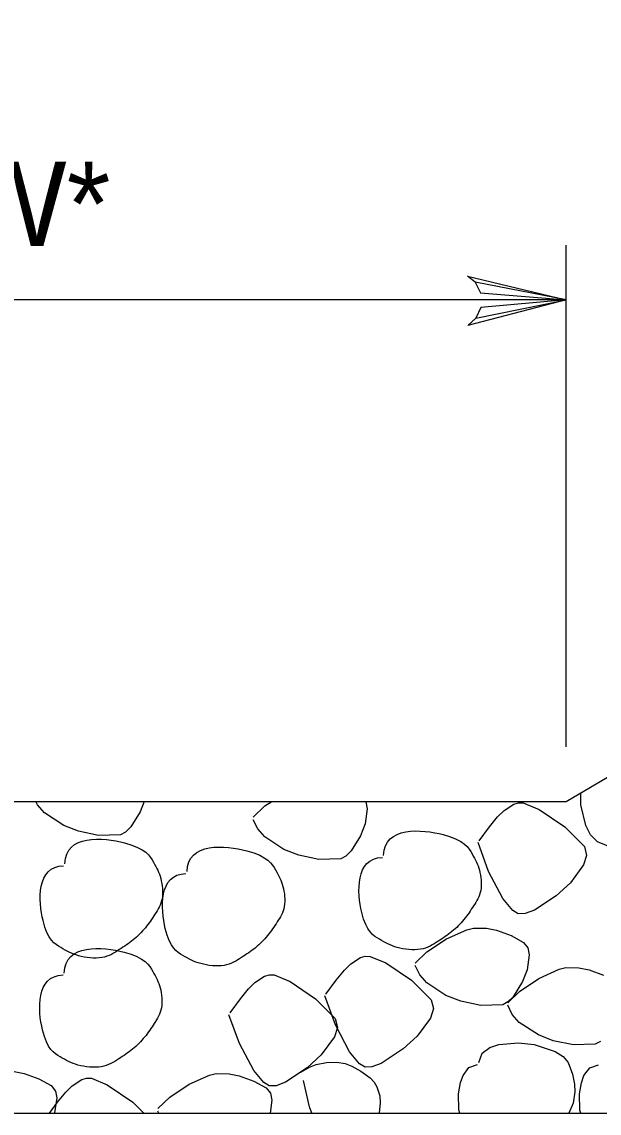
# Model space of a CAD drawing. Extents: x 636462 to 638208, y 299350 to 300538.
# Drawn here: x 637766.43 to 637786.9, y 299583.43 to 299622.12 of the extents above; entities that cross this region are included whole.
import ezdxf

# ---------------------------------------------------------------- set-up
doc = ezdxf.new("R2010")
doc.units = 0
doc.layers.add('Default', color=7, linetype='Continuous')

msp = doc.modelspace()

# ---------------------------------------------------------------- linework, layer by layer
at = {"layer": 'Default'}
for p, q in [((637785.737, 299596.416), (637785.737, 299614.199)), ((637785.737, 299612.265), (637747.043, 299612.265)), ((637786.257, 299594.359), (637786.248, 299594.783)), ((637766.984, 299594.355), (637766.919, 299594.481)), ((637770.77, 299594.481), (637770.63, 299594.113)), ((637775.048, 299594.318), (637775.296, 299594.481)), ((637778.613, 299594.481), (637778.629, 299594.461)), ((637778.629, 299594.461), (637778.675, 299594.214)), ((637783.53, 299594.154), (637783.874, 299594.382)), ((637783.874, 299594.382), (637784.044, 299594.431)), ((637784.044, 299594.431), (637784.214, 299594.424)), ((637784.214, 299594.424), (637784.779, 299594.198)), ((637767.233, 299594.069), (637766.984, 299594.355)), ((637767.914, 299593.625), (637767.233, 299594.069)), ((637770.63, 299594.113), (637770.296, 299593.574)), ((637774.633, 299593.919), (637775.048, 299594.318)), ((637778.675, 299594.214), (637778.599, 299593.685)), ((637783.302, 299593.929), (637783.53, 299594.154)), ((637784.779, 299594.198), (637785.682, 299593.579)), ((637786.428, 299593.627), (637786.257, 299594.359)), ((637768.442, 299593.422), (637767.914, 299593.625)), ((637774.794, 299593.507), (637774.633, 299593.832)), ((637778.599, 299593.685), (637778.44, 299593.265)), ((637783.01, 299593.574), (637783.302, 299593.929)), ((637786.598, 299593.293), (637786.428, 299593.627)), ((637769.151, 299593.272), (637768.442, 299593.422)), ((637769.925, 299593.295), (637769.151, 299593.272)), ((637770.109, 299593.392), (637769.925, 299593.295)), ((637770.296, 299593.574), (637770.109, 299593.392)), ((637775.043, 299593.222), (637774.794, 299593.507)), ((637775.725, 299592.775), (637775.043, 299593.222)), ((637778.44, 299593.265), (637778.106, 299592.726)), ((637782.651, 299593.083), (637783.01, 299593.574)), ((637785.682, 299593.579), (637786.379, 299592.883)), ((637786.849, 299593.047), (637786.598, 299593.293)), ((637782.984, 299591.996), (637782.607, 299593.017)), ((637786.379, 299592.883), (637786.46, 299592.567)), ((637787.303, 299592.862), (637786.849, 299593.047)), ((637776.254, 299592.572), (637775.725, 299592.775)), ((637776.962, 299592.422), (637776.254, 299592.572)), ((637777.738, 299592.448), (637776.962, 299592.422)), ((637777.92, 299592.542), (637777.738, 299592.448)), ((637778.106, 299592.726), (637777.92, 299592.542)), ((637786.46, 299592.567), (637786.354, 299592.233)), ((637786.354, 299592.233), (637785.882, 299591.593)), ((637783.487, 299591.036), (637782.984, 299591.996)), ((637785.882, 299591.593), (637785.384, 299591.137)), ((637783.839, 299590.61), (637783.487, 299591.036)), ((637785.384, 299591.137), (637784.608, 299590.626)), ((637784.035, 299590.495), (637783.839, 299590.61)), ((637784.608, 299590.626), (637784.279, 299590.501)), ((637784.279, 299590.501), (637784.035, 299590.495)), ((637781.49, 299589.606), (637782.208, 299589.93)), ((637782.208, 299589.93), (637782.446, 299589.99)), ((637782.446, 299589.99), (637782.904, 299589.986)), ((637782.904, 299589.986), (637783.263, 299589.91)), ((637783.263, 299589.91), (637783.784, 299589.721)), ((637780.794, 299589.145), (637781.49, 299589.606)), ((637783.784, 299589.721), (637784.219, 299589.483)), ((637784.219, 299589.483), (637784.373, 299589.288)), ((637778.436, 299588.947), (637778.608, 299588.995)), ((637778.608, 299588.995), (637778.776, 299588.986)), ((637778.776, 299588.986), (637779.341, 299588.76)), ((637780.377, 299588.746), (637780.794, 299589.145)), ((637784.422, 299589.041), (637784.346, 299588.509)), ((637784.373, 299589.288), (637784.422, 299589.041)), ((637777.867, 299588.491), (637778.092, 299588.716)), ((637778.092, 299588.716), (637778.436, 299588.947)), ((637779.341, 299588.76), (637780.244, 299588.141)), ((637780.538, 299588.332), (637780.377, 299588.657)), ((637785.49, 299588.528), (637785.725, 299588.585)), ((637785.725, 299588.585), (637786.184, 299588.581)), ((637786.184, 299588.581), (637786.545, 299588.507)), ((637774.695, 299588.055), (637775.038, 299588.283)), ((637775.038, 299588.283), (637775.211, 299588.332)), ((637775.211, 299588.332), (637775.379, 299588.325)), ((637775.379, 299588.325), (637775.944, 299588.097)), ((637777.574, 299588.138), (637777.867, 299588.491)), ((637780.787, 299588.049), (637780.538, 299588.332)), ((637784.074, 299587.742), (637784.769, 299588.203)), ((637784.346, 299588.509), (637784.187, 299588.09)), ((637784.769, 299588.203), (637785.49, 299588.528)), ((637786.545, 299588.507), (637787.063, 299588.318)), ((637774.177, 299587.475), (637774.467, 299587.83)), ((637774.467, 299587.83), (637774.695, 299588.055)), ((637775.944, 299588.097), (637776.846, 299587.48)), ((637777.213, 299587.648), (637777.574, 299588.138)), ((637780.244, 299588.141), (637780.942, 299587.447)), ((637781.469, 299587.602), (637780.787, 299588.049)), ((637784.187, 299588.09), (637783.85, 299587.551)), ((637773.815, 299586.984), (637774.177, 299587.475)), ((637776.846, 299587.48), (637777.544, 299586.784)), ((637777.549, 299586.561), (637777.169, 299587.581)), ((637780.942, 299587.447), (637781.024, 299587.132)), ((637781.999, 299587.399), (637781.469, 299587.602)), ((637783.659, 299587.344), (637784.074, 299587.742)), ((637783.85, 299587.551), (637783.664, 299587.369)), ((637781.024, 299587.132), (637780.918, 299586.798)), ((637782.706, 299587.249), (637781.999, 299587.399)), ((637783.482, 299587.272), (637782.706, 299587.249)), ((637783.664, 299587.369), (637783.482, 299587.272)), ((637783.821, 299586.929), (637783.659, 299587.254)), ((637774.149, 299585.897), (637773.772, 299586.918)), ((637777.544, 299586.784), (637777.627, 299586.469)), ((637780.918, 299586.798), (637780.444, 299586.158)), ((637784.067, 299586.644), (637783.821, 299586.929)), ((637784.749, 299586.199), (637784.067, 299586.644)), ((637777.627, 299586.469), (637777.521, 299586.135)), ((637778.049, 299585.6), (637777.549, 299586.561)), ((637774.651, 299584.937), (637774.149, 299585.897)), ((637777.521, 299586.135), (637777.047, 299585.494)), ((637780.444, 299586.158), (637779.949, 299585.702)), ((637783.351, 299585.865), (637784.046, 299585.92)), ((637784.046, 299585.92), (637784.599, 299585.856)), ((637785.278, 299585.996), (637784.749, 299586.199)), ((637785.988, 299585.847), (637785.278, 299585.996)), ((637786.762, 299585.87), (637785.988, 299585.847)), ((637786.946, 299585.966), (637786.762, 299585.87)), ((637777.047, 299585.494), (637776.549, 299585.038)), ((637778.403, 299585.174), (637778.049, 299585.6)), ((637779.949, 299585.702), (637779.17, 299585.19)), ((637782.637, 299585.218), (637782.759, 299585.554)), ((637782.759, 299585.554), (637783.026, 299585.757)), ((637783.026, 299585.757), (637783.351, 299585.865)), ((637784.599, 299585.856), (637785.343, 299585.614)), ((637785.343, 299585.614), (637785.622, 299585.432)), ((637776.632, 299585.054), (637776.872, 299585.146)), ((637776.872, 299585.146), (637777.236, 299585.222)), ((637777.236, 299585.222), (637777.597, 299585.236)), ((637777.597, 299585.236), (637777.901, 299585.183)), ((637777.901, 299585.183), (637778.127, 299585.098)), ((637778.127, 299585.098), (637778.456, 299584.914)), ((637778.599, 299585.057), (637778.403, 299585.174)), ((637779.17, 299585.19), (637778.841, 299585.064)), ((637782.287, 299585.043), (637782.591, 299585.151)), ((637785.622, 299585.432), (637785.806, 299585.218)), ((637785.806, 299585.218), (637785.963, 299584.812)), ((637786.578, 299585.034), (637786.882, 299585.142)), ((637766.15, 299584.909), (637766.51, 299584.833)), ((637766.51, 299584.833), (637767.028, 299584.644)), ((637772.367, 299584.449), (637773.085, 299584.773)), ((637773.085, 299584.773), (637773.32, 299584.831)), ((637773.32, 299584.831), (637773.781, 299584.826)), ((637773.781, 299584.826), (637774.14, 299584.753)), ((637774.14, 299584.753), (637774.658, 299584.564)), ((637775.006, 299584.511), (637774.651, 299584.937)), ((637776.549, 299585.038), (637775.773, 299584.527)), ((637776.324, 299584.879), (637776.632, 299585.054)), ((637778.456, 299584.914), (637778.779, 299584.677)), ((637778.841, 299585.064), (637778.599, 299585.057)), ((637781.985, 299584.513), (637782.075, 299584.766)), ((637782.075, 299584.766), (637782.287, 299585.043)), ((637785.963, 299584.812), (637786.027, 299584.46)), ((637786.276, 299584.506), (637786.366, 299584.76)), ((637786.366, 299584.76), (637786.578, 299585.034)), ((637767.028, 299584.644), (637767.463, 299584.407)), ((637767.463, 299584.407), (637767.62, 299584.211)), ((637767.984, 299584.168), (637768.209, 299584.393)), ((637768.209, 299584.393), (637768.552, 299584.621)), ((637768.552, 299584.621), (637768.725, 299584.67)), ((637768.725, 299584.67), (637768.893, 299584.663)), ((637768.893, 299584.663), (637769.458, 299584.435)), ((637769.458, 299584.435), (637770.361, 299583.817)), ((637771.671, 299583.988), (637772.367, 299584.449)), ((637774.658, 299584.564), (637775.096, 299584.327)), ((637775.2, 299584.393), (637775.006, 299584.511)), ((637775.096, 299584.327), (637775.25, 299584.131)), ((637775.444, 299584.4), (637775.2, 299584.393)), ((637775.773, 299584.527), (637775.444, 299584.4)), ((637776.632, 299583.656), (637776.413, 299584.589)), ((637778.779, 299584.677), (637778.926, 299584.525)), ((637778.926, 299584.525), (637779.021, 299584.363)), ((637779.021, 299584.363), (637779.12, 299584.046)), ((637781.92, 299584.117), (637781.985, 299584.513)), ((637786.027, 299584.46), (637786.036, 299584.184)), ((637786.211, 299584.108), (637786.276, 299584.506)), ((637767.666, 299583.965), (637767.59, 299583.435)), ((637767.62, 299584.211), (637767.666, 299583.965)), ((637767.691, 299583.813), (637767.984, 299584.168)), ((637771.254, 299583.589), (637771.671, 299583.988)), ((637775.25, 299584.131), (637775.299, 299583.884)), ((637779.12, 299584.046), (637779.14, 299583.792)), ((637781.932, 299583.539), (637781.92, 299584.117)), ((637786.036, 299584.184), (637785.981, 299583.783)), ((637786.223, 299583.53), (637786.211, 299584.108)), ((637767.408, 299583.426), (637767.691, 299583.813)), ((637770.361, 299583.817), (637770.752, 299583.426)), ((637775.299, 299583.884), (637775.232, 299583.426)), ((637776.713, 299583.426), (637776.632, 299583.656)), ((637779.14, 299583.792), (637779.099, 299583.431)), ((637785.981, 299583.783), (637785.829, 299583.431)), ((637767.59, 299583.435), (637767.587, 299583.426)), ((637771.291, 299583.426), (637771.254, 299583.5)), ((637779.099, 299583.431), (637779.097, 299583.426)), ((637781.957, 299583.426), (637781.932, 299583.539)), ((637785.829, 299583.431), (637785.827, 299583.426)), ((637786.248, 299583.426), (637786.223, 299583.53))]:
    msp.add_line(p, q, dxfattribs=at)
for points in [[(637700.057, 299622.12), (637747.043, 299594.481), (637785.737, 299594.481), (637832.723, 299622.12)], [(637782.501, 299612.884), (637782.231, 299613.106), (637785.737, 299612.265), (637782.501, 299612.884), (637782.7, 299612.512), (637785.737, 299612.265), (637782.709, 299611.989), (637782.529, 299611.612), (637785.737, 299612.265), (637782.248, 299611.357), (637782.529, 299611.612)], [(637703.462, 299607.291), (637703.461, 299607.29), (637744.03, 299583.426), (637788.747, 299583.426), (637829.316, 299607.29), (637829.315, 299607.291)]]:
    msp.add_lwpolyline(points, dxfattribs=at)
for points in [[(637779.258, 299592.561), (637779.273, 299593.618), (637781.977, 299593.378), (637782.429, 299592.561), (637782.684, 299592.1), (637782.773, 299591.27), (637782.45, 299590.776), (637782.13, 299590.286), (637781.688, 299589.843), (637781.199, 299589.525), (637780.633, 299589.156), (637779.67, 299589.268), (637779.147, 299589.569), (637778.402, 299589.997), (637778.239, 299592.47), (637779.214, 299592.494)], [(637767.954, 299592.268), (637767.967, 299593.325), (637770.672, 299593.085), (637771.125, 299592.268), (637771.381, 299591.807), (637771.472, 299590.975), (637771.148, 299590.481), (637770.828, 299589.992), (637770.386, 299589.55), (637769.898, 299589.232), (637769.33, 299588.863), (637768.367, 299588.976), (637767.843, 299589.276), (637767.098, 299589.704), (637766.935, 299592.18), (637767.91, 299592.201)], [(637772.288, 299591.989), (637772.302, 299593.046), (637775.006, 299592.807), (637775.46, 299591.989), (637775.715, 299591.529), (637775.806, 299590.699), (637775.483, 299590.204), (637775.163, 299589.715), (637774.72, 299589.272), (637774.232, 299588.954), (637773.665, 299588.584), (637772.701, 299588.697), (637772.178, 299588.997), (637771.433, 299589.426), (637771.27, 299591.899), (637772.245, 299591.923)], [(637767.933, 299588.394), (637767.948, 299589.451), (637770.652, 299589.212), (637771.104, 299588.394), (637771.359, 299587.934), (637771.448, 299587.103), (637771.125, 299586.609), (637770.805, 299586.119), (637770.363, 299585.676), (637769.875, 299585.358), (637769.308, 299584.989), (637768.345, 299585.102), (637767.822, 299585.402), (637767.077, 299585.83), (637766.914, 299588.306), (637767.889, 299588.327)]]:
    msp.add_open_spline(points, degree=3, dxfattribs=at)

# ---------------------------------------------------------------- texts
msp.add_text('W*', height=2.998, dxfattribs=at).set_placement((637764.232, 299614.167))

doc.saveas('drawing.dxf')
